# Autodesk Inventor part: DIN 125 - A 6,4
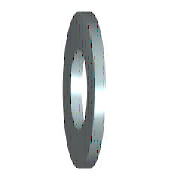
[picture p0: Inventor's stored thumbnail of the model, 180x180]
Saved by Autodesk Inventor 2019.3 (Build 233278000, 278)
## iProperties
Created: 2018-01
Part Number: DIN 125 - A 6,4
Material: Ocel, měkká
Description: Podložka
Document SubType Name: Modeling
Standard: DIN 125
Designer: B-hon
Standards Organization: DIN
Language: cs-CZ
Size Designation: A 6,4
Categories: <MemberInstance><Categories><Category DisplayName="Spojovací materiál" InternalName="e4da775c-781d-43d5-af7c-5136215cf5a6" Mnemonic="FSTN"><Category DisplayName
Density: 7.85 g/cm^3
Appearance: Pololeštěná
IsCustomPart: 0
Author: B-hon
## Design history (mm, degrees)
sketch "Náčrt"
  geometry: C1 r 6 at (0, 0); C2 r 3.2 at (0, 0); 1 further point
  constraints: 2 centre point, 2 coincident
  dimensions: "d0" = 6.4 diameter of C2 (= SD1); "d1" = 12 diameter of C1 (= SD2)
extrude "Těleso" new body sketch "Náčrt" distance "d2" = 1.6 (= SD); taper "d3" = 0 deg
workaxis "Work Axis1"
workplane "Work Plane1"
body "Solid1"
other parameters: "SD1" = 6.4 [user parameter; used in 1 equation term], "SD2" = 12 [user parameter; used in 1 equation term], "SD" = 1.6 [user parameter; used in 1 equation term], "d4" = 0, "d5" = 0, "d6" = 0, "d7" = 0, "NND" = 6 [user parameter]
